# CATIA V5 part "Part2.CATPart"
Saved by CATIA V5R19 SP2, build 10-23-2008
Part number: Bâti
Publications: "Dav", "Dac"
Bounding box of the stored display mesh (mm): x -200 to 0, y -300 to 300, z 0 to 450
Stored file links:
  C:\Users\Vianney\Documents\Garantie\Cours\2A\IAO\IAO-proj-Catia\Part2.CATPart
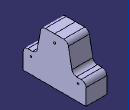
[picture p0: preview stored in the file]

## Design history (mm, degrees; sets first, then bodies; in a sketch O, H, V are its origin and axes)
Parameters
  Hb = 450 mm
  Hb2 = 200 mm
  Dav = 20 mm
  Dac = 15 mm
  AngleCAD = 90 deg
  Eb = 100 mm
Body1 (main body)
  Sketch1 on yz-plane, origin (0, 0, 0), H (0, 1, 0), V (0, 0, 1)
    point P1 (-173.196, 200)
    line L1 (-173.196, 200) -> (-300, 200)
    point P2 (-300, 200)
    line L2 (-300, 200) -> (-300, 0)
    point P3 (-300, 0)
    line L3 (-300, 0) -> (0, 0)
    arc A1 centre (0, 375) radius 10 from (0, 385) to (0, 365) ccw
    point P4 (0, 375)
    point P5 (0, 365)
    point P6 (0, 385)
    circle A2 centre (-225, 150) radius 7.5
    point P7 (-225, 150)
    axis line L4 (-225, 150) -> (0, 375)
    line L5 (-126.0047, 450) -> (0, 450)
    point P8 (-126.0047, 450)
    point P9 (0, 450)
    line L6 (-173.196, 200) -> (-126.0047, 450)
    point P10 (0, 0)
    point P11 (173.196, 200)
    point P12 (300, 200)
    point P13 (300, 0)
    point P15 (0, 365)
    point P16 (0, 385)
    construction line L7 (225, 150) -> (0, 375)
    point P18 (126.0047, 450)
    point P19 (0, 450)
    line L8 (173.196, 200) -> (300, 200)
    line L9 (300, 200) -> (300, 0)
    line L10 (300, 0) -> (0, 0)
    arc A3 centre (0, 375) radius 10 from (0, 385) to (0, 365) cw
    circle A4 centre (225, 150) radius 7.5
    line L11 (126.0047, 450) -> (0, 450)
    line L12 (173.196, 200) -> (126.0047, 450)
    length L3 = 300 {= Hb -Hb /3}
    distance L1 L3 = 200 {= Hb2}
    radius A1 = 10 {= Dav /2}
    radius A2 = 7.5 {= Dac /2}
    angle L4 V = 45 {= AngleCAD /2}
    distance P4 V = 0
    distance L3 L5 = 450 {= Hb}
    distance P4 L3 = 375 {= Hb -Hb /6}
    distance P7 L1 = 50 {= Hb2/4}
    perpendicularity: L3 L2
    horizontal: L3 H
    symmetry: O P10 V, P1 P11 V, P2 P12 V, P3 P13 V, P5 P15 V, P6 P16 V, L4 L7 V, P8 P18 V, P9 P19 V, L1 L8 V, L2 L9 V, L3 L10 V, A1 A3 V, A2 A4 V, L5 L11 V, L6 L12 V
    coincidence: O P10, P5 P15, P6 P16, P9 P19
    fix: L6
  Pad1: profile Sketch1, direction (-1, 0, 0), length 200
  Fillet1: radius 45, on edge [face of Pad1 from Sketch1.L1 | face of Pad1 from Sketch1.L2]; edge [face of Pad1 from Sketch1.L6 | face of Pad1 from Sketch1.L1]; edge [face of Pad1 from Sketch1.L5 | face of Pad1 from Sketch1.L6]; edge [face of Pad1 from Sketch1.L12 | face of Pad1 from Sketch1.L11]; edge [face of Pad1 from Sketch1.L8 | face of Pad1 from Sketch1.L12]; edge [face of Pad1 from Sketch1.L9 | face of Pad1 from Sketch1.L8]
